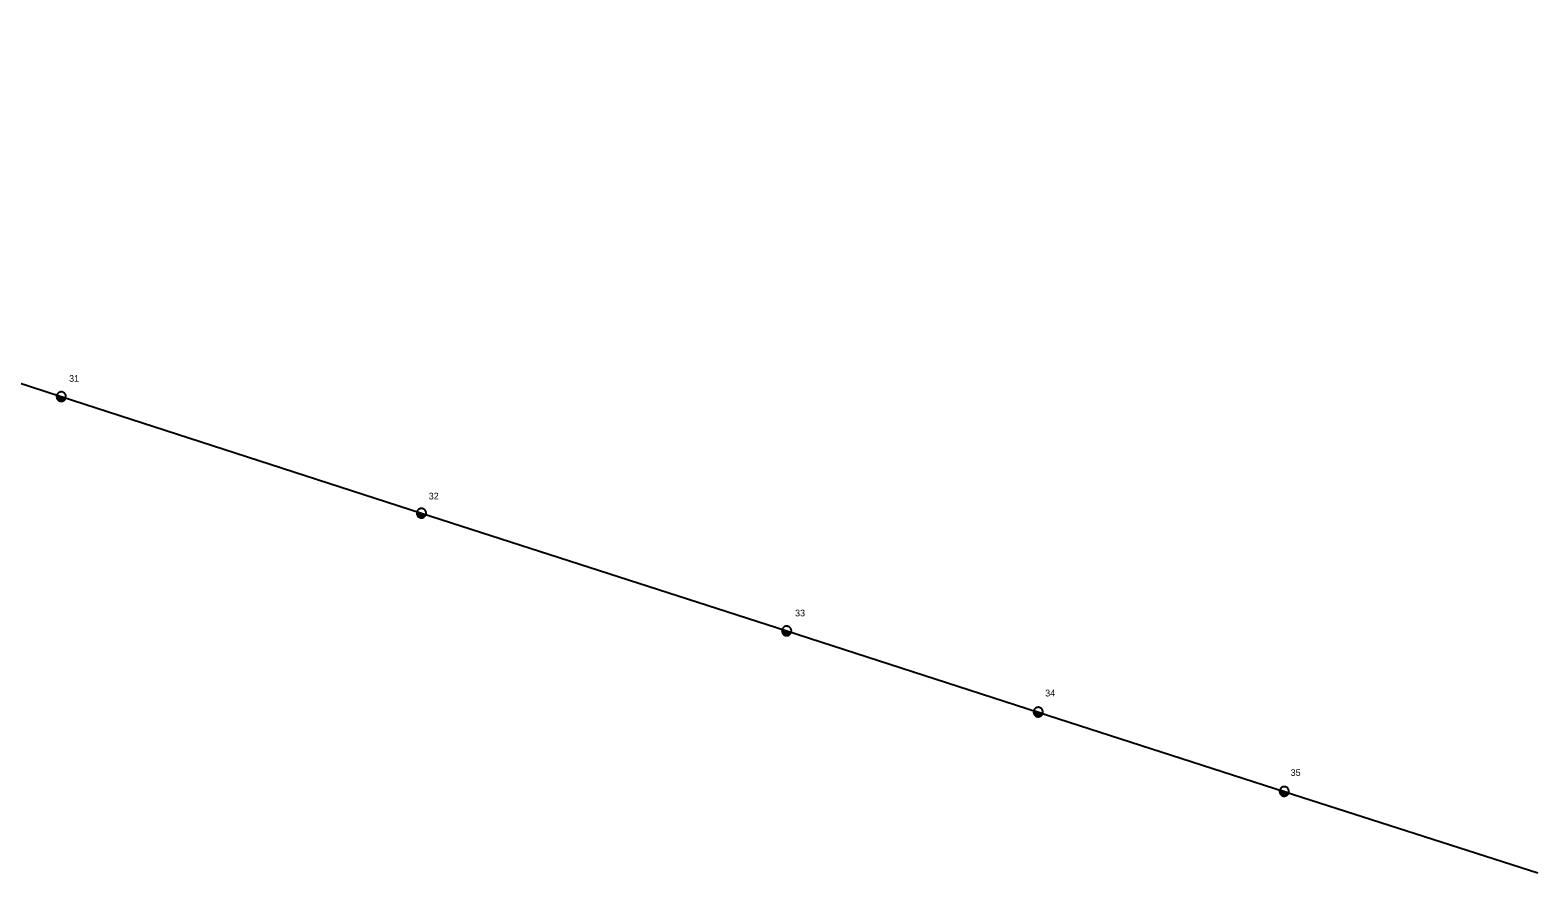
# Model space of a CAD drawing. Extents: x -761250 to -760338, y -1155000 to -1154503.
# Drawn here: x -760731.1 to -760337.8, y -1155000 to -1154780 of the extents above; entities that cross this region are included whole.
import ezdxf

# ---------------------------------------------------------------- set-up
doc = ezdxf.new("R2010")
doc.units = 0
for name, color, linetype in [('Vrstva 1', 7, 'Continuous'), ('Vrstva 13', 7, 'Continuous'), ('Vrstva 14', 7, 'Continuous')]:
    doc.layers.add(name, color=color, linetype=linetype)

msp = doc.modelspace()

# ---------------------------------------------------------------- linework, layer by layer
at = {"layer": 'Vrstva 1'}
msp.add_lwpolyline([(-761250, -1154560.04), (-761239.44, -1154568.33), (-761186.98, -1154609.48), (-761124.95, -1154658.28), (-761056.6, -1154711.35), (-760986.69, -1154766.03), (-760934.04, -1154806.89), (-760877.08, -1154825.6), (-760813.81, -1154846.09), (-760723.01, -1154875.68), (-760629.06, -1154906.1), (-760533.78, -1154936.84), (-760468.16, -1154958.01), (-760403.99, -1154978.73), (-760337.85, -1155000)], dxfattribs=at)
at = {"layer": 'Vrstva 13'}
for points in [[(-760721.845, -1154876.04), (-760721.814, -1154875.915), (-760721.796, -1154875.788), (-760721.792, -1154875.659), (-760721.8, -1154875.531), (-760721.823, -1154875.404), (-760721.858, -1154875.281), (-760721.906, -1154875.161), (-760721.966, -1154875.048), (-760722.038, -1154874.941), (-760722.121, -1154874.843), (-760722.213, -1154874.753), (-760722.315, -1154874.674), (-760722.424, -1154874.606), (-760722.54, -1154874.55), (-760722.661, -1154874.506), (-760722.785, -1154874.475), (-760722.913, -1154874.457), (-760723.041, -1154874.452), (-760723.169, -1154874.461), (-760723.296, -1154874.483), (-760723.419, -1154874.519), (-760723.539, -1154874.567), (-760723.652, -1154874.628), (-760723.759, -1154874.7), (-760723.857, -1154874.782), (-760723.946, -1154874.874), (-760724.026, -1154874.976), (-760724.094, -1154875.085), (-760724.15, -1154875.2), (-760724.194, -1154875.321), (-760724.226, -1154875.446), (-760724.243, -1154875.573), (-760724.248, -1154875.702), (-760724.239, -1154875.831), (-760724.216, -1154875.957), (-760724.181, -1154876.08), (-760724.133, -1154876.2), (-760724.072, -1154876.313), (-760724.001, -1154876.42), (-760723.918, -1154876.518), (-760723.825, -1154876.608), (-760723.724, -1154876.687), (-760723.615, -1154876.755), (-760723.499, -1154876.811), (-760723.379, -1154876.855), (-760723.254, -1154876.886), (-760723.127, -1154876.904), (-760722.998, -1154876.909), (-760722.87, -1154876.9), (-760722.743, -1154876.878), (-760722.619, -1154876.842), (-760722.5, -1154876.794), (-760722.387, -1154876.733), (-760722.28, -1154876.661), (-760722.182, -1154876.579), (-760722.093, -1154876.487), (-760722.014, -1154876.385), (-760721.945, -1154876.276), (-760721.889, -1154876.161), (-760721.845, -1154876.04)], [(-760724.241, -1154875.66), (-760722.057, -1154876.328)], [(-760724.195, -1154875.313), (-760721.846, -1154876.031)], [(-760724.16, -1154875.986), (-760722.27, -1154876.564)], [(-760723.987, -1154876.34), (-760722.629, -1154876.755)], [(-760627.895, -1154906.46), (-760627.864, -1154906.335), (-760627.846, -1154906.208), (-760627.842, -1154906.079), (-760627.85, -1154905.951), (-760627.873, -1154905.824), (-760627.908, -1154905.701), (-760627.956, -1154905.581), (-760628.016, -1154905.468), (-760628.088, -1154905.361), (-760628.171, -1154905.262), (-760628.264, -1154905.173), (-760628.365, -1154905.094), (-760628.474, -1154905.026), (-760628.59, -1154904.97), (-760628.711, -1154904.926), (-760628.835, -1154904.895), (-760628.963, -1154904.877), (-760629.091, -1154904.872), (-760629.219, -1154904.881), (-760629.346, -1154904.903), (-760629.469, -1154904.939), (-760629.589, -1154904.987), (-760629.702, -1154905.048), (-760629.809, -1154905.12), (-760629.907, -1154905.202), (-760629.996, -1154905.294), (-760630.076, -1154905.396), (-760630.144, -1154905.505), (-760630.2, -1154905.62), (-760630.244, -1154905.741), (-760630.276, -1154905.866), (-760630.293, -1154905.993), (-760630.298, -1154906.122), (-760630.289, -1154906.251), (-760630.266, -1154906.377), (-760630.231, -1154906.5), (-760630.183, -1154906.619), (-760630.123, -1154906.733), (-760630.051, -1154906.84), (-760629.968, -1154906.938), (-760629.875, -1154907.028), (-760629.774, -1154907.107), (-760629.665, -1154907.175), (-760629.549, -1154907.231), (-760629.429, -1154907.275), (-760629.304, -1154907.306), (-760629.177, -1154907.324), (-760629.048, -1154907.329), (-760628.92, -1154907.32), (-760628.794, -1154907.298), (-760628.669, -1154907.262), (-760628.55, -1154907.214), (-760628.437, -1154907.153), (-760628.33, -1154907.081), (-760628.232, -1154906.999), (-760628.143, -1154906.907), (-760628.064, -1154906.805), (-760627.995, -1154906.696), (-760627.939, -1154906.581), (-760627.895, -1154906.46)], [(-760630.245, -1154905.733), (-760627.896, -1154906.451)], [(-760630.291, -1154906.08), (-760628.107, -1154906.748)], [(-760630.21, -1154906.406), (-760628.32, -1154906.984)], [(-760630.037, -1154906.76), (-760628.68, -1154907.175)], [(-760532.615, -1154937.2), (-760532.584, -1154937.075), (-760532.566, -1154936.948), (-760532.562, -1154936.819), (-760532.57, -1154936.691), (-760532.593, -1154936.564), (-760532.628, -1154936.441), (-760532.676, -1154936.321), (-760532.736, -1154936.208), (-760532.808, -1154936.101), (-760532.891, -1154936.002), (-760532.984, -1154935.913), (-760533.085, -1154935.834), (-760533.194, -1154935.766), (-760533.31, -1154935.71), (-760533.431, -1154935.666), (-760533.555, -1154935.635), (-760533.683, -1154935.617), (-760533.811, -1154935.612), (-760533.939, -1154935.621), (-760534.066, -1154935.643), (-760534.189, -1154935.679), (-760534.309, -1154935.727), (-760534.422, -1154935.788), (-760534.529, -1154935.86), (-760534.627, -1154935.942), (-760534.716, -1154936.034), (-760534.796, -1154936.136), (-760534.864, -1154936.245), (-760534.92, -1154936.36), (-760534.964, -1154936.481), (-760534.996, -1154936.606), (-760535.013, -1154936.733), (-760535.018, -1154936.862), (-760535.009, -1154936.991), (-760534.986, -1154937.117), (-760534.951, -1154937.24), (-760534.903, -1154937.359), (-760534.843, -1154937.473), (-760534.771, -1154937.58), (-760534.688, -1154937.678), (-760534.595, -1154937.768), (-760534.494, -1154937.847), (-760534.385, -1154937.915), (-760534.269, -1154937.971), (-760534.149, -1154938.015), (-760534.024, -1154938.046), (-760533.897, -1154938.064), (-760533.768, -1154938.069), (-760533.64, -1154938.06), (-760533.514, -1154938.038), (-760533.389, -1154938.002), (-760533.27, -1154937.954), (-760533.157, -1154937.893), (-760533.05, -1154937.821), (-760532.952, -1154937.739), (-760532.863, -1154937.647), (-760532.784, -1154937.545), (-760532.715, -1154937.436), (-760532.659, -1154937.321), (-760532.615, -1154937.2)], [(-760535.011, -1154936.82), (-760532.827, -1154937.488)], [(-760534.965, -1154936.473), (-760532.616, -1154937.191)], [(-760534.93, -1154937.146), (-760533.04, -1154937.724)], [(-760534.757, -1154937.5), (-760533.399, -1154937.915)], [(-760466.995, -1154958.37), (-760466.964, -1154958.245), (-760466.946, -1154958.118), (-760466.942, -1154957.989), (-760466.95, -1154957.861), (-760466.973, -1154957.734), (-760467.008, -1154957.611), (-760467.056, -1154957.491), (-760467.116, -1154957.378), (-760467.188, -1154957.271), (-760467.271, -1154957.172), (-760467.364, -1154957.083), (-760467.465, -1154957.004), (-760467.574, -1154956.936), (-760467.69, -1154956.88), (-760467.811, -1154956.836), (-760467.935, -1154956.805), (-760468.063, -1154956.787), (-760468.191, -1154956.782), (-760468.319, -1154956.791), (-760468.446, -1154956.813), (-760468.569, -1154956.849), (-760468.689, -1154956.897), (-760468.802, -1154956.958), (-760468.909, -1154957.03), (-760469.007, -1154957.112), (-760469.096, -1154957.204), (-760469.176, -1154957.306), (-760469.244, -1154957.415), (-760469.3, -1154957.53), (-760469.344, -1154957.651), (-760469.376, -1154957.776), (-760469.393, -1154957.903), (-760469.398, -1154958.032), (-760469.389, -1154958.161), (-760469.366, -1154958.287), (-760469.331, -1154958.41), (-760469.283, -1154958.529), (-760469.223, -1154958.643), (-760469.151, -1154958.75), (-760469.068, -1154958.848), (-760468.975, -1154958.938), (-760468.874, -1154959.017), (-760468.765, -1154959.085), (-760468.649, -1154959.141), (-760468.529, -1154959.185), (-760468.404, -1154959.216), (-760468.277, -1154959.234), (-760468.148, -1154959.239), (-760468.02, -1154959.23), (-760467.894, -1154959.208), (-760467.769, -1154959.172), (-760467.65, -1154959.124), (-760467.537, -1154959.063), (-760467.43, -1154958.991), (-760467.332, -1154958.909), (-760467.243, -1154958.817), (-760467.164, -1154958.715), (-760467.095, -1154958.606), (-760467.039, -1154958.491), (-760466.995, -1154958.37)], [(-760469.391, -1154957.99), (-760467.207, -1154958.658)], [(-760469.345, -1154957.643), (-760466.996, -1154958.361)], [(-760469.31, -1154958.316), (-760467.42, -1154958.894)], [(-760469.137, -1154958.67), (-760467.779, -1154959.085)], [(-760402.825, -1154979.09), (-760402.794, -1154978.965), (-760402.776, -1154978.838), (-760402.772, -1154978.709), (-760402.78, -1154978.581), (-760402.803, -1154978.454), (-760402.838, -1154978.331), (-760402.886, -1154978.211), (-760402.946, -1154978.098), (-760403.018, -1154977.991), (-760403.101, -1154977.892), (-760403.194, -1154977.803), (-760403.295, -1154977.724), (-760403.404, -1154977.656), (-760403.52, -1154977.6), (-760403.641, -1154977.556), (-760403.765, -1154977.525), (-760403.893, -1154977.507), (-760404.021, -1154977.502), (-760404.149, -1154977.511), (-760404.276, -1154977.533), (-760404.399, -1154977.569), (-760404.519, -1154977.617), (-760404.632, -1154977.678), (-760404.739, -1154977.75), (-760404.837, -1154977.832), (-760404.926, -1154977.924), (-760405.006, -1154978.026), (-760405.074, -1154978.135), (-760405.13, -1154978.25), (-760405.174, -1154978.371), (-760405.206, -1154978.496), (-760405.223, -1154978.623), (-760405.228, -1154978.752), (-760405.219, -1154978.881), (-760405.196, -1154979.007), (-760405.161, -1154979.13), (-760405.113, -1154979.249), (-760405.053, -1154979.363), (-760404.981, -1154979.47), (-760404.898, -1154979.568), (-760404.805, -1154979.658), (-760404.704, -1154979.737), (-760404.595, -1154979.805), (-760404.479, -1154979.861), (-760404.359, -1154979.905), (-760404.234, -1154979.936), (-760404.107, -1154979.954), (-760403.978, -1154979.959), (-760403.85, -1154979.95), (-760403.724, -1154979.928), (-760403.599, -1154979.892), (-760403.48, -1154979.844), (-760403.367, -1154979.783), (-760403.26, -1154979.711), (-760403.162, -1154979.629), (-760403.073, -1154979.537), (-760402.994, -1154979.435), (-760402.925, -1154979.326), (-760402.869, -1154979.211), (-760402.825, -1154979.09)], [(-760405.221, -1154978.71), (-760403.037, -1154979.378)], [(-760405.175, -1154978.363), (-760402.826, -1154979.081)], [(-760405.14, -1154979.036), (-760403.25, -1154979.614)], [(-760404.967, -1154979.39), (-760403.61, -1154979.805)]]:
    msp.add_lwpolyline(points, dxfattribs=at)

# ---------------------------------------------------------------- texts
at = {"layer": 'Vrstva 14'}
for s, p in [('31', (-760720.97, -1154871.82)), ('32', (-760627.15, -1154902.52)), ('33', (-760531.6, -1154933.05)), ('34', (-760466.36, -1154953.95)), ('35', (-760402.33, -1154974.7))]:
    msp.add_text(s, height=1.74, dxfattribs=at).set_placement(p)

doc.saveas('drawing.dxf')
